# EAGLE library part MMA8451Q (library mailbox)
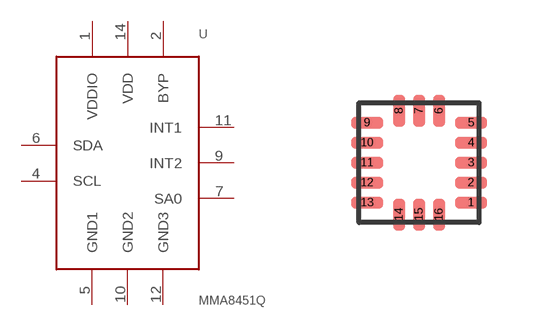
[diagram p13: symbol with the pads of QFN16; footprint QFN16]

Designator prefix -

## MMA8451Q  [QFN16]
1  VDDIO
2  BYP
4  SCL
5  GND1
6  SDA
7  SA0
9  INT2
10  GND2
11  INT1
12  GND3
14  VDD

## Footprint QFN16 (pad centres in mm)
smd 0.8 x 0.3: 1 0.8,0.5; 2 0.8,1; 3 0.8,1.5; 4 0.8,2; 5 0.8,2.5; 9 -1.8,2.5; 10 -1.8,2; 11 -1.8,1.5; 12 -1.8,1; 13 -1.8,0.5
smd 0.3 x 0.8: 6 0,2.8; 7 -0.5,2.8; 8 -1,2.8; 14 -1,0.2; 15 -0.5,0.2; 16 0,0.2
